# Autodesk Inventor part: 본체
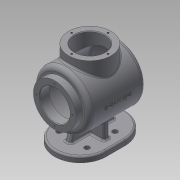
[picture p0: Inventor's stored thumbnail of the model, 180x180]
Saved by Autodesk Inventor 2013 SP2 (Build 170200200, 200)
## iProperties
Created: 2023-01
Part Number: 본체
Material: Generic
Document SubType Name: Modeling
Designer: i
Density: 1 g/cm^3
Author: i
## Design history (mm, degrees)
sketch "스케치1"
  geometry: L1 (-46, 34)-(-46, 0); L2 (46, 34)-(46, 0); L3 (0, 80)-(0, -46); A1 r 46 centre (0, 0) between (-46, 0) and (46, 0); A2 r 46 centre (0, 34) between (46, 34) and (-46, 34); 1 further point
  constraints: 6 end point, 6 point on circle, 4 tangent, 2 centre point, 2 coincident, 1 equal radius, 1 vertical alignment
  dimensions: "d10" = 92 diameter of A1; "d12" = 126 distance of L3.start L3.end
extrude "돌출1" new body sketch "스케치1" distance "d13" = 10; taper "d14" = 0 deg
node "작업 평면3"
  node "작업 평면2"
node "작업 평면4"
sketch "스케치9"
  geometry: L1 (-130, -34)-(-80, -34); L2 (-80, -34)-(-80, 76); L3 (-80, 76)-(-130, 76); L4 (-130, 76)-(-130, 65.087); L5 (0, 0)-(0, 0) reference; L6 (0, 0)-(-10, 0) reference; L7 (-10, 0)-(-10, 0) reference; L8 (0, 0)-(-10, 0) reference; L9 (0, 0)-(0, -46) reference; L10 (0, 0)-(0, 34) reference; L11 (0, 34)-(-10, 34) reference; L12 (-10, 0)-(-10, 34) reference; L13 (0, 0)-(-10, 0) reference; L14 (-16.796, 17)-(-185.396, 17); L15 (0, 0)-(0, 34) reference; L16 (-130, 65.087)-(-130, -34); L17 (-80, -29)-(-85.344, -29); L18 (-85.344, -29)-(-125, -29); L19 (-125, -29)-(-125, -24.092); L20 (-125, -24.092)-(-125, 61.83); L21 (-125, 61.83)-(-125, 76); A1 r 120 centre (-80, -44) between (-183.339, 17) and (-80, 76); A2 r 120 centre (-80, -44) between (-130, 65.087) and (-183.339, 17); A3 r 120 centre (-80, -44) between (-80, 76) and (-130, 65.087); A4 r 115 centre (-80, -44) between (-130, 59.562) and (-80, 71); A5 r 115 centre (-80, -44) between (-125, 61.83) and (-130, 59.562); A6 r 115 centre (-80, -44) between (-80, 71) and (-125, 61.83); 1 further point
  constraints: 22 end point, 12 point on circle, 7 point on line, 6 centre point, 6 parallel, 3 perpendicular, 2 tangent, 1 concentric, 1 horizontal, 1 horizontal alignment, 1 midpoint
  dimensions: "d51" = 80 distance from line of L9 L1.end; "d52" = 100 diameter of L4 L2; "d53" = 51 distance from line of L14 L1.start; "d56" = 59 distance from line of L14 L2.end; "d57" = 5 distance between parallel lines of L1 L18; "d58" = 5 distance between parallel lines of L16 L19; "d124" = 5 distance of L2.end A4.end; "d125" = 240 diameter of A3
revolve "회전1" sketch "스케치9" stored, may be unused: angle "d60" = 90 deg
sketch "스케치10"
  geometry: C1 r 50 at (0, 0) reference; C2 r 38 at (0, 0); 1 further point
  constraints: 1 centre point, 1 coincident
  dimensions: "d61" = 76 diameter of C2
extrude "돌출7" join sketch "스케치10" distance "d63" = 12; taper "d64" = 0 deg
sketch "스케치11"
  geometry: C1 r 38 at (0, 0) reference; C2 r 27 at (0, 0); 1 further point
  constraints: 1 centre point, 1 coincident
  dimensions: "d65" = 54 diameter of C2
extrude "돌출8" cut sketch "스케치11" distance "d67" = 17; taper "d68" = 0 deg
sketch "스케치8"
  geometry: L1 (-46, 34)-(-46, 0) reference; L2 (-30, 22)-(30, 22); L3 (30, 22)-(30, 12); L4 (30, 12)-(-30, 12); L5 (-30, 12)-(-30, 22); L6 (-46, 34)-(-46, 0) reference; L7 (46, 0)-(46, 34) reference; A1 r 46 centre (0, 34) between (46, 34) and (-46, 34) reference; A2 r 46 centre (0, 0) between (-46, 0) and (46, 0) reference; A3 r 46 centre (0, 34) between (46, 34) and (-46, 34) reference; 4 further points
  constraints: 8 end point, 3 midpoint, 2 parallel, 1 horizontal, 1 horizontal alignment, 1 perpendicular, 1 point on circle, 1 vertical alignment
  dimensions: "d45" = 60 distance of L2.start L2.end; "d47" = 10 distance of L4.end L2.start
extrude "돌출6" join sketch "스케치8" stored distance "d48" = 40; taper "d49" = 0 deg
sketch "스케치13" dims "d73" = 65
  geometry: C1 r 27 at (0, 0) reference; C2 r 38 at (0, 0) reference; 3 further points
  constraints: 2 vertical alignment, 1 coincident, 2 other
hole "구멍1" sketch "스케치13" at (0, 32.5) diameter "d75" = 3.242; stored, may be unused: countersink angle "d79" = 90 deg, drill point angle "d81" = 118 deg; dims "d76" = 8, "d77" = 4, "d78" = 2, "d80" = 10
node "작업 평면7"
sketch "스케치14"
  geometry: L1 (-46, 34)-(-46, 0) reference; L2 (46, 0)-(46, 34) reference; L3 (-30, 22)-(30, 22) reference; L4 (30, 22)-(30, 12) reference; L5 (30, 12)-(-30, 12) reference; L6 (-30, 12)-(-30, 22) reference; C1 r 38 at (0, 17); A1 r 46 centre (0, 0) between (-46, 0) and (46, 0) reference; A2 r 46 centre (0, 34) between (46, 34) and (-46, 34) reference; 3 further points
  constraints: 1 centre point, 1 horizontal alignment, 1 midpoint, 1 point on circle, 1 vertical alignment
  dimensions: "d86" = 76 diameter of C1
extrude "돌출9" join sketch "스케치14" stored distance "d89" = 90; taper "d90" = 0 deg
sketch "스케치15"
  geometry: C1 r 38 at (0, 0) reference; C2 r 27 at (0, 0); 1 further point
  constraints: 1 centre point, 1 coincident
  dimensions: "d91" = 54 diameter of C2
extrude "돌출10" cut sketch "스케치15" distance "d93" = 50; taper "d94" = 0 deg
sketch "스케치16" dims "d95" = 65
  geometry: C1 r 27 at (0, 0) reference; C2 r 38 at (0, 0) reference; 3 further points
  constraints: 2 vertical alignment, 1 coincident, 2 other
hole "구멍2" sketch "스케치16" at (0, 32.5) diameter "d97" = 3.242; stored, may be unused: countersink angle "d101" = 90 deg, drill point angle "d103" = 118 deg; dims "d98" = 8, "d99" = 4, "d100" = 2, "d102" = 10
chamfer "모따기1" distance "d107" = 1; stored, may be unused: second distance "d108" = 2, angle "d109" = 45 deg
sketch "스케치17"
  geometry: L1 (-35, -16.301)-(-10, -23); L2 (-10, -23)-(-10, 57); L3 (-10, 57)-(-35, 50.301); L4 (-35, 50.301)-(-35, -16.301); L5 (0, 0)-(0, -46); L6 (0, 0)-(0, 34) reference; L7 (0, 34)-(-10, 34) reference; L8 (-10, 0)-(-10, 34) reference; L9 (0, 0)-(-10, 0) reference; L10 (-10, 0)-(-10, 34) reference; 2 further points
  constraints: 10 end point, 2 midpoint, 2 parallel, 1 coincident, 1 equal length, 1 vertical
  dimensions: "d116" = 105 deg angle of L2 L1; "d117" = 25 distance between parallel lines of L2 L4; "d119" = 80 distance of L1.end L2.end; "d120" = 46 distance of L5.start L5.end; "d121" = 23 vertical distance of L5.end L1.end
extrude "돌출11" join sketch "스케치17" stored distance "d122" = 10; taper "d123" = 0 deg
fillet "모깎기1" dims "d126" = 8
fillet "모깎기2" dims "d127" = 3
fillet "모깎기3" dims "d128" = 3
sketch "스케치18"
  geometry: L1 (2, 59.302)-(-2, 59.302) reference; L2 (33, 15)-(33, 19) reference; L3 (-2, -25.302)-(2, -25.302) reference; L4 (-33, 19)-(-33, 15) reference; L5 (-5, -25.302)-(-5, 59.302); L6 (-33, 17)-(33, 17); 5 further points
  constraints: 4 end point, 2 midpoint, 2 point on line
  dimensions: "d129" = 30 horizontal distance of L5.start point (25, -13); "d131" = 30 distance from line of L6 point (25, -13)
hole "구멍3" sketch "스케치18" at (25, -13) diameter "d132" = 9; stored, may be unused: countersink angle "d136" = 90 deg, drill point angle "d138" = 0 deg; dims "d133" = 8, "d134" = 4, "d135" = 2, "d137" = 10
node "작업 평면9"
sketch "스케치19"
  geometry: L1 (-61.544, 38)-(-61.544, -38) reference; L2 (-49.544, -38)-(-49.544, 38) reference; 2 further points
  constraints: 1 other
  dimensions: "d145" = 63 distance from line of L1 point (1.456, 0); "d146" = 80 vertical distance of point (-15.544, -80) point (1.456, 0)
feature "엠보싱1" sketch "스케치19" dims "d147" = 0.5, "d148" = 0
node "솔리드1"
pattern_circular "원형 패턴1" dims angle "d83" = 360 deg
pattern_circular "원형 패턴2" dims angle "d105" = 360 deg
pattern_linear "직사각형 패턴1" dims "d141" = 50
node "투영된 루프3"
node "투영된 루프4"
node "투영된 루프5"
node "투영된 루프7"
node "투영된 루프9"
node "투영된 루프10"
other parameters: "d22" = 63, "d39" = -46, "d85" = 134
